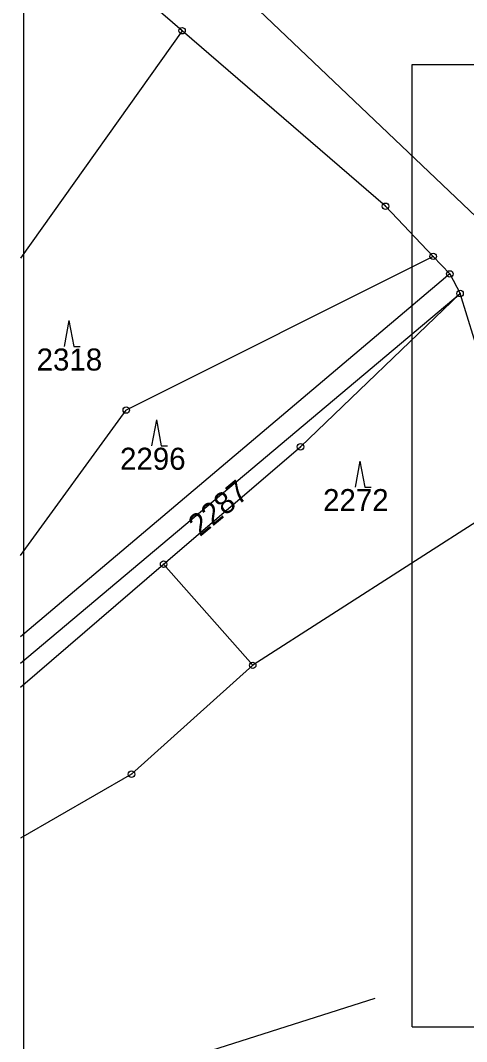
# Model space of a CAD drawing. Extents: x -566461 to -565198, y -1096301 to -1095707.
# Drawn here: x -566458.9 to -566390.1, y -1095956.2 to -1095798.6 of the extents above; entities that cross this region are included whole.
import ezdxf

# ---------------------------------------------------------------- set-up
doc = ezdxf.new("R2010")
doc.units = 0
for name, color, linetype in [('Vrstva 1', 7, 'Continuous'), ('Vrstva 18', 7, 'Continuous'), ('Vrstva 24', 7, 'Continuous'), ('Vrstva 25', 7, 'Continuous'), ('Vrstva 63', 7, 'Continuous')]:
    doc.layers.add(name, color=color, linetype=linetype)

msp = doc.modelspace()

# ---------------------------------------------------------------- linework, layer by layer
at = {"layer": 'Vrstva 1'}
for p, q in [((-566458.91, -1095762.04), (-566383.43, -1095833.87)), ((-566433.97, -1095800.22), (-566458.91, -1095778.71)), ((-566433.97, -1095800.22), (-566458.91, -1095835.3)), ((-566402.58, -1095827.3), (-566433.97, -1095800.22)), ((-566395.23, -1095835.03), (-566402.58, -1095827.3)), ((-566395.23, -1095835.03), (-566442.58, -1095858.74)), ((-566392.64, -1095837.75), (-566395.23, -1095835.03)), ((-566392.64, -1095837.75), (-566458.91, -1095893.73)), ((-566392.64, -1095837.75), (-566391.07, -1095840.75)), ((-566458.91, -1095897.78), (-566391.07, -1095840.75)), ((-566391.07, -1095840.75), (-566415.7, -1095864.42)), ((-566387.83, -1095851.23), (-566391.07, -1095840.75)), ((-566458.91, -1095881.18), (-566442.58, -1095858.74)), ((-566436.81, -1095882.52), (-566415.7, -1095864.42)), ((-566385.12, -1095873.77), (-566423.07, -1095898.13)), ((-566458.91, -1095901.49), (-566436.81, -1095882.52)), ((-566423.07, -1095898.13), (-566436.81, -1095882.52)), ((-566423.07, -1095898.13), (-566441.77, -1095914.92)), ((-566441.77, -1095914.92), (-566458.91, -1095924.8)), ((-566404.24, -1095949.53), (-566455.45, -1095965.82))]:
    msp.add_line(p, q, dxfattribs=at)
at = {"layer": 'Vrstva 24'}
for centre, radius in [((-566433.97, -1095800.22), 0.5), ((-566433.97, -1095800.22), 0.0327), ((-566402.58, -1095827.3), 0.5), ((-566402.58, -1095827.3), 0.0327), ((-566395.23, -1095835.03), 0.5), ((-566395.23, -1095835.03), 0.0327), ((-566392.64, -1095837.75), 0.5), ((-566392.64, -1095837.75), 0.0327), ((-566391.07, -1095840.75), 0.5), ((-566391.07, -1095840.75), 0.0327), ((-566442.58, -1095858.74), 0.5), ((-566442.58, -1095858.74), 0.0327), ((-566415.7, -1095864.42), 0.5), ((-566415.7, -1095864.42), 0.0327), ((-566436.81, -1095882.52), 0.5), ((-566436.81, -1095882.52), 0.0327), ((-566423.07, -1095898.13), 0.5), ((-566423.07, -1095898.13), 0.0327), ((-566441.77, -1095914.92), 0.5), ((-566441.77, -1095914.92), 0.0327)]:
    msp.add_circle(centre, radius, dxfattribs=at)
at = {"layer": 'Vrstva 25'}
for p, q in [((-566451.42, -1095844.94), (-566452.16, -1095848.94)), ((-566451.42, -1095844.94), (-566450.69, -1095848.94)), ((-566450.69, -1095848.94), (-566449.69, -1095848.94)), ((-566437.92, -1095860.25), (-566438.66, -1095864.25)), ((-566437.92, -1095860.25), (-566437.19, -1095864.25)), ((-566437.19, -1095864.25), (-566436.19, -1095864.25)), ((-566406.52, -1095866.63), (-566407.26, -1095870.63)), ((-566406.52, -1095866.63), (-566405.79, -1095870.63)), ((-566405.79, -1095870.63), (-566404.79, -1095870.63))]:
    msp.add_line(p, q, dxfattribs=at)
at = {"layer": 'Vrstva 63'}
for p, q in [((-566458.38, -1096301.03), (-566458.38, -1095707.03)), ((-566398.46, -1095953.91), (-566398.46, -1095805.41)), ((-566398.46, -1095805.41), (-566188.46, -1095805.41)), ((-566398.46, -1095953.91), (-566293.46, -1095953.91))]:
    msp.add_line(p, q, dxfattribs=at)

# ---------------------------------------------------------------- texts
at = {"layer": 'Vrstva 18'}
for s, p in [('2318', (-566456.41, -1095852.65)), ('2296', (-566443.54, -1095867.96)), ('2272', (-566412.21, -1095874.34))]:
    msp.add_text(s, height=3.4, dxfattribs=at).set_placement(p)
msp.add_text('2287', height=3.4, rotation=39.6, dxfattribs=at).set_placement((-566431.21, -1095878.37))

doc.saveas('drawing.dxf')
